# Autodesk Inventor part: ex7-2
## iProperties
Shininess: 64.0
Length Units: 11272
Angle Units: 11279
Time Units: 11290
Mass Units: 11286
Length Display Precision: 3
Angle Display Precision: 2
Compacted: True
Part Number: ex7-2
Document SubType Name: Modeling
Created: 2002-11
Designer: Elise Moss
Density: 0.0
Volumn: 0.0
Area: 0.0
PropertySet Name: Model Information
Control State: 0
Master: False
Checked Out: False
Author: Elise Moss
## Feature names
1. Hole1
2. Base1
